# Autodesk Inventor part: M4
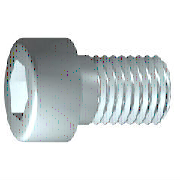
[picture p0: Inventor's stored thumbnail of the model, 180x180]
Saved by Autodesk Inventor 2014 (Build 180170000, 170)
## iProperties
IsCustomPart: 0
Created: 2014-10
Part Number: M4
Material: 강철, 연강
Description: 6각머리 태핑 나사
Document SubType Name: Modeling
Standard: KS B 1003
Designer: KYOUNG IL JANG
Standards Organization: KS
Language: ko-KR
Size Designation: M 4 x 10
Categories: <MemberInstance><Categories><Category DisplayName="조임쇠" InternalName="e4da775c-781d-43d5-af7c-5136215cf5a6" Mnemonic="FSTN"><Category DisplayName="볼트" InternalN
Density: 7.86 g/cm^3
Mass: 2.0371 g
Surface Area: 3.0572 cm^2
Volume: 0.259174 cm^3
Appearance: Black Cast
Author: SeoGD™ [www.esajin.kr]
Revision Number: 1
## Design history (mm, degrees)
sketch "스케치1"
  geometry: L1 (-1, 0)-(10, 0); L2 (10, 0)-(10, 2); L3 (10, 2)-(1.75, 2); L4 (1.75, 2)-(1.32, 2); L5 (1.32, 2)-(0, 2); L6 (0, 2)-(0, 3.5); L7 (0, 3.5)-(-4, 3.5); L8 (-4, 3.5)-(-4, 1.732); L9 (-4, 1.732)-(-2, 1.732); L10 (-2, 1.732)-(-1, 0); L11 (-6.8, 0)-(12.8, 0) reference; L12 (0, -0.7)-(0, 4.2) reference; L13 (1.75, 2)-(0, 2)
  constraints: 22 end point, 6 parallel, 2 collinear, 2 perpendicular, 1 horizontal, 1 point on line
  dimensions: "d1" = 8.25 distance from line of L3.end L2 (= GEL); "d2" = 0.42952 distance of L4.end L3.end (computed from GAL); "d3" = 4 distance between parallel lines of L8 L6 (= KOH); "d4" = 2 distance of L8.end L9.end (= INTI); "d5" = 60 deg angle of L10 L1; "d6" = 4 diameter of L3 L1 (= GD); "d7" = 4 diameter of L5 L1 (= BDM); "d8" = 3.4641 diameter of L9 L1 (= 1.1547 x SW); "d9" = 7 diameter of L7 L1 (= KOD); "d26" = 10 distance between parallel lines of L12 L2 (= NLG)
revolve "본체" sketch "스케치1" stored, may be unused: angle "d10" = 90 deg
sketch "스케치2"
  geometry: L1 (0, -4.9)-(0, 4.9) reference; L2 (-4.9, 0)-(4.9, 0) reference; L3 (1.732, 0)-(0.866, -1.5); L4 (0.866, -1.5)-(-0.866, -1.5); L5 (-0.866, -1.5)-(-1.732, 0); L6 (-1.732, 0)-(-0.866, 1.5); L7 (-0.866, 1.5)-(0.866, 1.5); L8 (0.866, 1.5)-(1.732, 0); 2 further points
  constraints: 12 end point, 1 coincident, 1 horizontal alignment, 1 point on line, 12 other
extrude "슬롯" join sketch "스케치2" stored distance "d11" = 10; taper "d12" = 0 deg
workplane "Work Plane1"
fillet "Fillet2" dims "d30" = 0.1 (= R)
body "Solid1"
fillet "모깎기1" dims "d17" = 0.4 (= RR)
feature "스레드" dims "d13" = 8.25 (= GEL), "d14" = 0
chamfer "모따기1" distance "d15" = 0.42941 (= -0.5 x SPD + 0.5 x GD); stored, may be unused: second distance "d16" = 0.42941 (= GUL), angle "d27" = 45 deg
other parameters: "GD" = 4 (= NND) [user parameter; used in 2 equation terms], "NLG" = 10 [user parameter; used in 1 equation term], "GEL" = 8.25 [user parameter; used in 2 equation terms], "KOD" = 7 [user parameter; used in 1 equation term], "KOH" = 4 [user parameter; used in 1 equation term], "INTI" = 2 [user parameter; used in 1 equation term], "GAL" = 0.42941 (= 0.61345 x PTC) [user parameter; used in 1 equation term], "GUL" = 0.42941 (= 0.61345 x PTC) [user parameter; used in 1 equation term], "BDM" = 4 (= NND) [user parameter; used in 1 equation term], "SW" = 3 [user parameter; used in 2 equation terms], "RR" = 0.4 [user parameter; used in 1 equation term], "SPD" = 3.14117 (= NND - 1.2269 x PTC) [user parameter; used in 1 equation term], "d19" = 0, "d28" = 0, "d29" = 0, "R" = 0.1 [user parameter; used in 1 equation term], "PHH" = 0.2 [user parameter], "GD1" = 3.14117 (= THREADDIA - 1.2269 x PTC) [user parameter], "THREADDIA" = 4 [user parameter; used in 1 equation term], "FAWI" = 45 deg [user parameter], "TPU" = 14.28571 (computed from PTC) [user parameter], "PTC" = 0.7 [user parameter; used in 5 equation terms], "NND" = 4 [user parameter; used in 3 equation terms], "TOA" = 30 deg [user parameter], "E0" = 3.465 (= 1.155 x SW) [user parameter]
